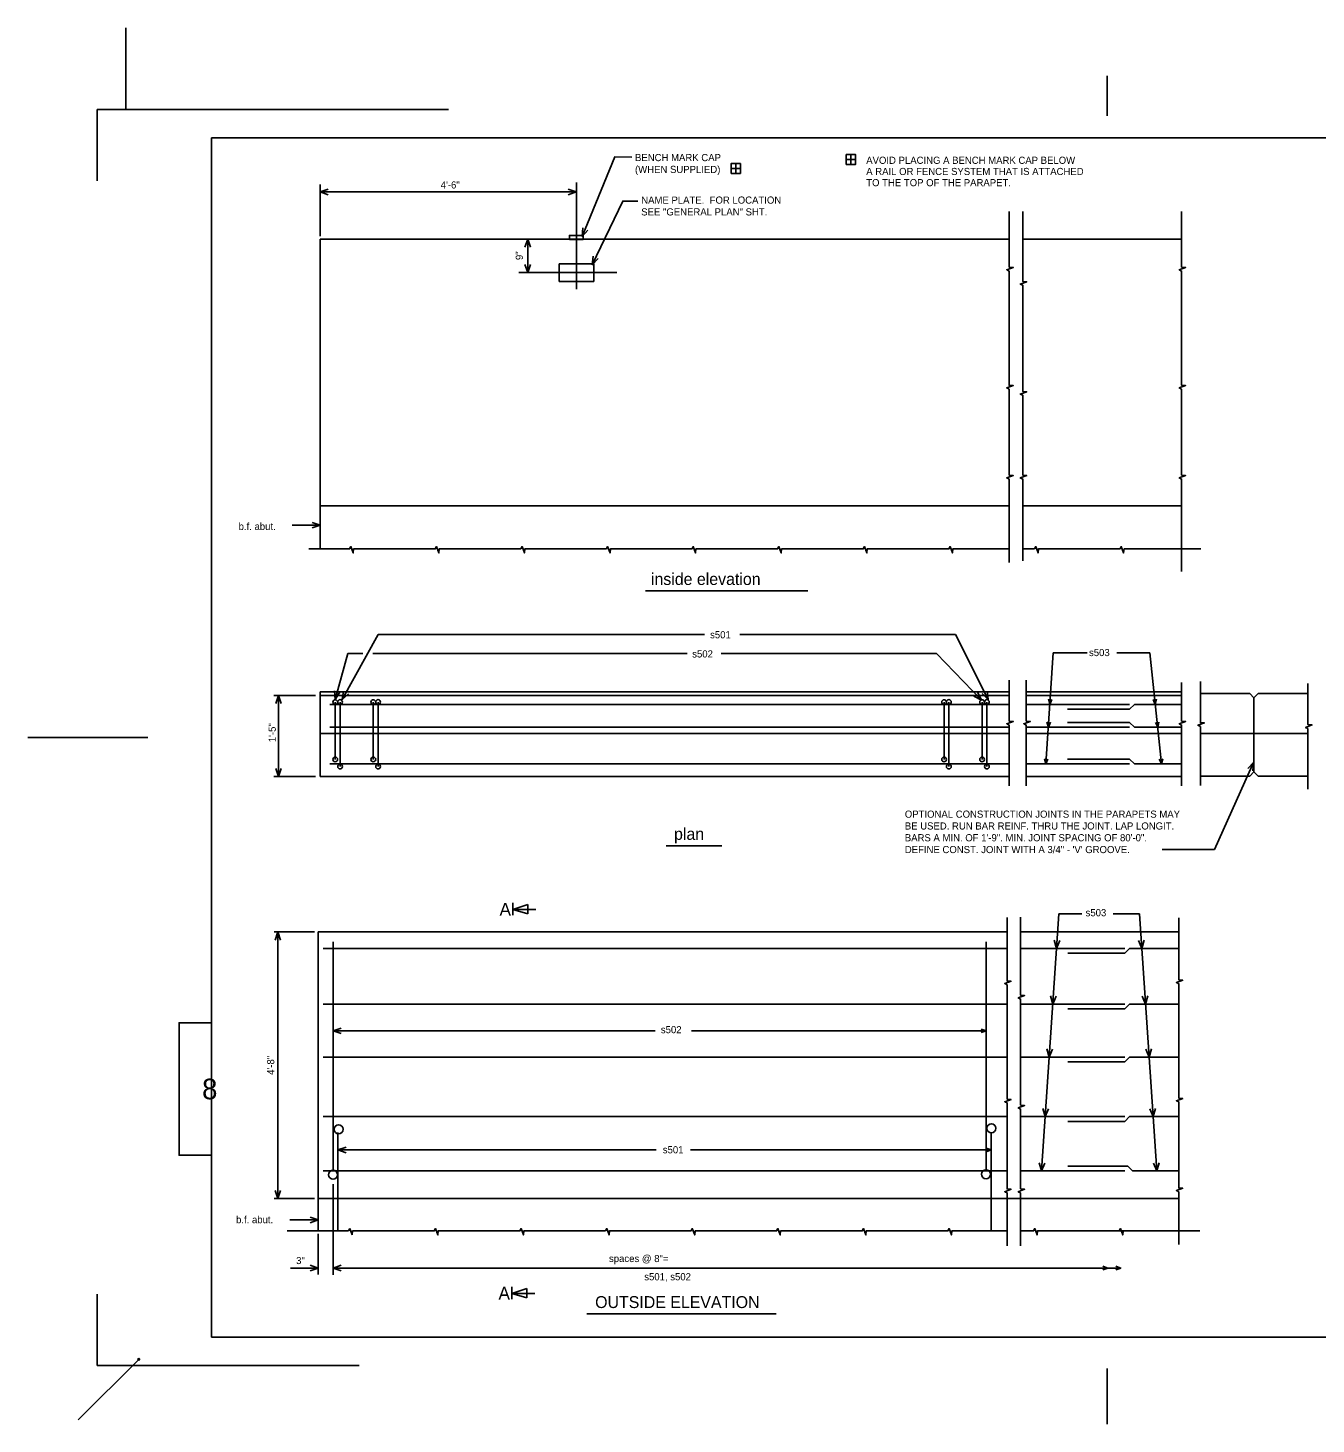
# Model space of a CAD drawing. Extents: x -38.4 to -2.2, y 84.9 to 109.4.
# Drawn here: x -38.4 to -15.84, y 84.95 to 109.4 of the extents above; entities that cross this region are included whole.
import ezdxf

# ---------------------------------------------------------------- set-up
doc = ezdxf.new("R2010")
doc.units = 0
for name, color, linetype in [('Default', 7, 'Continuous'), ('Level 1', 7, 'Continuous'), ('Level 2', 7, 'Continuous'), ('Level 37', 7, 'Continuous'), ('Level 49', 7, 'Continuous')]:
    doc.layers.add(name, color=color, linetype=linetype)

msp = doc.modelspace()

# ---------------------------------------------------------------- linework, layer by layer
at = {"layer": 'Default'}
for p, q in [((-33.278, 105.749), (-33.278, 106.654)), ((-28.787, 104.825), (-28.787, 106.689)), ((-33.278, 106.525), (-28.778, 106.525)), ((-21.212, 105.695), (-33.278, 105.695)), ((-33.278, 105.695), (-33.278, 101.028)), ((-29.644, 105.115), (-29.644, 105.698)), ((-18.191, 105.695), (-20.974, 105.695)), ((-29.095, 104.958), (-29.095, 105.264)), ((-29.095, 105.264), (-28.486, 105.264)), ((-28.486, 104.958), (-28.486, 105.264)), ((-29.801, 105.115), (-28.081, 105.115)), ((-29.095, 104.958), (-28.486, 104.958)), ((-33.278, 103.695), (-33.278, 103.664)), ((-21.212, 101.028), (-33.278, 101.028)), ((-33.278, 101.028), (-33.278, 100.274)), ((-18.191, 101.028), (-20.974, 101.028)), ((-33.772, 100.689), (-33.278, 100.689)), ((-27.579, 99.537), (-24.74, 99.537)), ((-32.897, 97.637), (-32.261, 98.773)), ((-32.261, 98.773), (-26.545, 98.773)), ((-25.929, 98.773), (-22.151, 98.773)), ((-21.577, 97.635), (-22.151, 98.773)), ((-33.018, 97.639), (-32.795, 98.443)), ((-32.795, 98.443), (-32.532, 98.443)), ((-32.357, 98.443), (-26.849, 98.443)), ((-26.254, 98.443), (-22.485, 98.443)), ((-21.697, 97.625), (-22.485, 98.443)), ((-33.362, 97.706), (-34.092, 97.706)), ((-34.008, 96.289), (-34.008, 97.706)), ((-21.212, 97.768), (-33.278, 97.768)), ((-33.278, 96.289), (-33.278, 97.768)), ((-21.212, 97.706), (-33.278, 97.706)), ((-33.016, 97.591), (-33.016, 96.587)), ((-32.931, 97.592), (-32.931, 96.462)), ((-32.349, 97.591), (-32.349, 96.587)), ((-32.265, 97.592), (-32.265, 96.462)), ((-22.352, 97.591), (-22.352, 96.587)), ((-22.268, 97.592), (-22.268, 96.462)), ((-21.686, 97.591), (-21.686, 96.587)), ((-21.601, 97.592), (-21.601, 96.462)), ((-18.191, 97.768), (-20.913, 97.768)), ((-18.191, 97.706), (-20.913, 97.706)), ((-17.863, 97.744), (-16.996, 97.744)), ((-16.925, 97.664), (-16.996, 97.744)), ((-16.853, 97.744), (-16.925, 97.664)), ((-16.925, 97.664), (-16.925, 96.368)), ((-16.853, 97.744), (-15.978, 97.744)), ((-21.212, 97.551), (-33.112, 97.551)), ((-19.101, 97.551), (-20.913, 97.551)), ((-19.101, 97.467), (-20.187, 97.467)), ((-18.191, 97.551), (-19.017, 97.551)), ((-21.212, 97.151), (-33.112, 97.151)), ((-19.101, 97.151), (-20.913, 97.151)), ((-19.101, 97.235), (-20.187, 97.235)), ((-18.191, 97.151), (-19.017, 97.151)), ((-21.212, 97.039), (-33.278, 97.039)), ((-20.913, 97.039), (-18.191, 97.039)), ((-17.863, 97.039), (-15.978, 97.039)), ((-20.187, 96.591), (-19.101, 96.591)), ((-33.112, 96.508), (-21.212, 96.508)), ((-20.913, 96.508), (-19.101, 96.508)), ((-19.017, 96.508), (-18.191, 96.508)), ((-17.614, 95.012), (-16.932, 96.533)), ((-16.925, 96.368), (-16.997, 96.296)), ((-16.925, 96.368), (-16.853, 96.296)), ((-33.362, 96.289), (-34.092, 96.289)), ((-21.212, 96.289), (-33.278, 96.289)), ((-18.191, 96.289), (-20.913, 96.289)), ((-17.863, 96.296), (-16.997, 96.296)), ((-16.853, 96.296), (-15.978, 96.296)), ((-27.221, 95.073), (-26.243, 95.073)), ((-18.53, 95.012), (-17.614, 95.012)), ((-29.907, 94.073), (-29.907, 93.858)), ((-29.907, 93.956), (-29.643, 94.044)), ((-29.643, 93.88), (-29.907, 93.956)), ((-29.907, 93.956), (-29.502, 93.956)), ((-29.643, 94.044), (-29.643, 93.88)), ((-20.645, 89.381), (-20.343, 93.882)), ((-20.343, 93.882), (-19.94, 93.882)), ((-18.927, 93.882), (-19.387, 93.882)), ((-18.625, 89.381), (-18.927, 93.882)), ((-33.378, 93.565), (-34.084, 93.565)), ((-34.021, 93.565), (-34.021, 88.898)), ((-33.315, 93.565), (-33.315, 88.329)), ((-33.315, 93.565), (-21.249, 93.565)), ((-21.011, 93.565), (-18.241, 93.565)), ((-21.249, 93.275), (-33.228, 93.275)), ((-33.053, 93.391), (-33.053, 89.381)), ((-21.614, 93.391), (-21.614, 89.381)), ((-19.184, 93.275), (-21.011, 93.275)), ((-19.184, 93.192), (-20.184, 93.192)), ((-18.241, 93.275), (-19.101, 93.275)), ((-21.249, 92.302), (-33.228, 92.302)), ((-19.184, 92.302), (-21.011, 92.302)), ((-19.184, 92.219), (-20.184, 92.219)), ((-18.241, 92.302), (-19.101, 92.302)), ((-33.053, 91.833), (-27.412, 91.833)), ((-26.776, 91.833), (-21.614, 91.833)), ((-21.249, 91.374), (-33.228, 91.374)), ((-19.184, 91.374), (-21.011, 91.374)), ((-19.184, 91.291), (-20.184, 91.291)), ((-18.241, 91.374), (-19.101, 91.374)), ((-21.249, 90.331), (-33.228, 90.331)), ((-19.184, 90.331), (-21.011, 90.331)), ((-19.184, 90.248), (-20.184, 90.248)), ((-18.241, 90.331), (-19.101, 90.331)), ((-32.968, 90.053), (-32.968, 88.329)), ((-21.529, 90.053), (-21.529, 88.329)), ((-32.968, 89.747), (-27.395, 89.747)), ((-26.795, 89.747), (-21.529, 89.747)), ((-21.249, 89.381), (-33.228, 89.381)), ((-19.184, 89.381), (-21.011, 89.381)), ((-19.135, 89.464), (-20.184, 89.464)), ((-18.241, 89.381), (-19.052, 89.381)), ((-33.053, 89.147), (-33.053, 87.563)), ((-33.378, 88.898), (-34.084, 88.898)), ((-33.315, 88.898), (-18.241, 88.898)), ((-33.808, 88.521), (-33.315, 88.521)), ((-33.855, 88.329), (-32.781, 88.329)), ((-33.315, 88.279), (-33.315, 87.568)), ((-32.781, 88.329), (-32.759, 88.371)), ((-32.759, 88.371), (-32.718, 88.259)), ((-32.718, 88.259), (-32.712, 88.329)), ((-32.712, 88.329), (-31.994, 88.329)), ((-33.802, 87.679), (-33.315, 87.679)), ((-33.053, 87.679), (-19.256, 87.679)), ((-19.908, 87.679), (-19.908, 87.679)), ((-29.924, 87.351), (-29.924, 87.135)), ((-29.924, 87.234), (-29.661, 87.322)), ((-29.661, 87.322), (-29.661, 87.158)), ((-29.661, 87.158), (-29.924, 87.234)), ((-29.924, 87.234), (-29.52, 87.234)), ((-28.606, 86.877), (-25.295, 86.877))]:
    msp.add_line(p, q, dxfattribs=at)
for points in [[(-28.69, 105.745), (-28.12, 107.137), (-27.82, 107.136)], [(-33.138, 106.476), (-33.278, 106.525), (-33.138, 106.573)], [(-28.936, 106.573), (-28.795, 106.525), (-28.936, 106.476)], [(-28.513, 105.251), (-27.981, 106.365), (-27.716, 106.365)], [(-21.212, 104.428), (-21.212, 105.14), (-21.253, 105.161), (-21.141, 105.203), (-21.212, 105.209), (-21.212, 106.181)], [(-20.974, 104.071), (-20.974, 104.89), (-21.016, 104.911), (-20.904, 104.952), (-20.974, 104.958), (-20.974, 106.181)], [(-18.191, 104.428), (-18.191, 105.14), (-18.233, 105.161), (-18.121, 105.203), (-18.191, 105.209), (-18.191, 106.181)], [(-28.591, 105.857), (-28.69, 105.745), (-28.681, 105.894)], [(-29.693, 105.557), (-29.644, 105.698), (-29.596, 105.557)], [(-28.408, 105.357), (-28.513, 105.251), (-28.496, 105.399)], [(-29.596, 105.256), (-29.644, 105.115), (-29.693, 105.256)], [(-21.212, 102.538), (-21.212, 103.07), (-21.253, 103.092), (-21.141, 103.133), (-21.212, 103.139), (-21.212, 104.421)], [(-18.191, 102.538), (-18.191, 103.07), (-18.233, 103.092), (-18.121, 103.133), (-18.191, 103.139), (-18.191, 104.421)], [(-20.974, 102.538), (-20.974, 102.964), (-21.016, 102.985), (-20.904, 103.027), (-20.974, 103.033), (-20.974, 104.158)], [(-21.212, 100.036), (-21.212, 101.496), (-21.253, 101.518), (-21.141, 101.559), (-21.212, 101.565), (-21.212, 102.538)], [(-20.974, 100.064), (-20.974, 101.496), (-21.016, 101.518), (-20.904, 101.559), (-20.974, 101.565), (-20.974, 102.538)], [(-18.191, 99.879), (-18.191, 101.496), (-18.233, 101.518), (-18.121, 101.559), (-18.191, 101.565), (-18.191, 102.538)], [(-33.419, 100.737), (-33.278, 100.689), (-33.419, 100.64)], [(-33.476, 100.274), (-32.764, 100.274), (-32.742, 100.315), (-32.701, 100.203), (-32.695, 100.274), (-31.976, 100.274)], [(-31.976, 100.274), (-31.264, 100.274), (-31.243, 100.315), (-31.201, 100.203), (-31.195, 100.274), (-30.477, 100.274)], [(-30.477, 100.274), (-29.765, 100.274), (-29.743, 100.315), (-29.702, 100.203), (-29.696, 100.274), (-28.978, 100.274)], [(-28.978, 100.274), (-28.265, 100.274), (-28.244, 100.315), (-28.202, 100.203), (-28.197, 100.274), (-27.478, 100.274)], [(-27.478, 100.274), (-26.766, 100.274), (-26.744, 100.315), (-26.703, 100.203), (-26.697, 100.274), (-25.979, 100.274)], [(-25.979, 100.274), (-25.267, 100.274), (-25.245, 100.315), (-25.204, 100.203), (-25.198, 100.274), (-24.479, 100.274)], [(-24.479, 100.274), (-23.767, 100.274), (-23.745, 100.315), (-23.704, 100.203), (-23.698, 100.274), (-22.98, 100.274)], [(-22.98, 100.274), (-22.268, 100.274), (-22.246, 100.315), (-22.205, 100.203), (-22.199, 100.274), (-21.48, 100.274)], [(-21.48, 100.274), (-21.212, 100.274)], [(-20.974, 100.274), (-20.768, 100.274), (-20.747, 100.315), (-20.705, 100.203), (-20.699, 100.274), (-19.981, 100.274)], [(-19.981, 100.274), (-19.269, 100.274), (-19.247, 100.315), (-19.206, 100.203), (-19.2, 100.274), (-17.852, 100.274)], [(-21.212, 96.127), (-21.212, 97.189), (-21.253, 97.211), (-21.141, 97.252), (-21.212, 97.258), (-21.212, 97.977)], [(-20.913, 96.127), (-20.913, 97.189), (-20.955, 97.211), (-20.843, 97.252), (-20.913, 97.258), (-20.913, 97.977)], [(-18.191, 96.127), (-18.191, 97.189), (-18.233, 97.211), (-18.121, 97.252), (-18.191, 97.258), (-18.191, 97.936)], [(-17.863, 96.132), (-17.863, 97.162), (-17.905, 97.184), (-17.793, 97.225), (-17.863, 97.231), (-17.863, 97.949)], [(-15.978, 96.064), (-15.978, 97.127), (-16.019, 97.148), (-15.907, 97.19), (-15.978, 97.196), (-15.978, 97.914)], [(-34.057, 97.565), (-34.008, 97.706), (-33.96, 97.565)], [(-32.934, 97.762), (-33.018, 97.639), (-33.028, 97.788)], [(-32.786, 97.736), (-32.897, 97.637), (-32.871, 97.783)], [(-21.76, 97.761), (-21.697, 97.625), (-21.83, 97.693)], [(-21.597, 97.783), (-21.577, 97.635), (-21.684, 97.739)], [(-33.96, 96.43), (-34.008, 96.289), (-34.057, 96.43)], [(-17.034, 96.425), (-16.932, 96.533), (-16.945, 96.385)], [(-21.249, 91.927), (-21.249, 92.639), (-21.29, 92.661), (-21.178, 92.702), (-21.249, 92.708), (-21.249, 93.818)], [(-21.011, 91.571), (-21.011, 92.389), (-21.052, 92.411), (-20.94, 92.452), (-21.011, 92.458), (-21.011, 93.825)], [(-18.241, 91.946), (-18.241, 92.658), (-18.283, 92.679), (-18.171, 92.721), (-18.241, 92.727), (-18.241, 93.812)], [(-34.07, 93.424), (-34.021, 93.565), (-33.972, 93.424)], [(-20.326, 93.413), (-20.384, 93.275), (-20.423, 93.419)], [(-18.944, 93.413), (-18.886, 93.275), (-18.847, 93.419)], [(-20.391, 92.439), (-20.449, 92.302), (-20.489, 92.446)], [(-18.879, 92.439), (-18.821, 92.302), (-18.781, 92.446)], [(-18.241, 90.055), (-18.241, 90.588), (-18.283, 90.61), (-18.171, 90.651), (-18.241, 90.657), (-18.241, 91.939)], [(-32.912, 91.785), (-33.053, 91.833), (-32.912, 91.882)], [(-21.702, 91.864), (-21.614, 91.833), (-21.702, 91.803)], [(-21.249, 90.037), (-21.249, 90.57), (-21.29, 90.591), (-21.178, 90.633), (-21.249, 90.638), (-21.249, 91.921)], [(-21.011, 90.037), (-21.011, 90.463), (-21.052, 90.485), (-20.94, 90.526), (-21.011, 90.532), (-21.011, 91.657)], [(-20.454, 91.512), (-20.512, 91.374), (-20.551, 91.518)], [(-18.816, 91.512), (-18.758, 91.374), (-18.719, 91.518)], [(-20.524, 90.468), (-20.582, 90.331), (-20.621, 90.475)], [(-18.746, 90.468), (-18.688, 90.331), (-18.649, 90.475)], [(-21.249, 88.07), (-21.249, 88.996), (-21.29, 89.017), (-21.178, 89.059), (-21.249, 89.065), (-21.249, 90.037)], [(-21.011, 88.07), (-21.011, 88.996), (-21.052, 89.017), (-20.94, 89.059), (-21.011, 89.065), (-21.011, 90.037)], [(-18.241, 88.089), (-18.241, 89.014), (-18.283, 89.036), (-18.171, 89.077), (-18.241, 89.083), (-18.241, 90.055)], [(-32.827, 89.698), (-32.968, 89.747), (-32.827, 89.796)], [(-21.617, 89.777), (-21.529, 89.747), (-21.617, 89.717)], [(-20.587, 89.518), (-20.645, 89.381), (-20.684, 89.524)], [(-18.683, 89.518), (-18.625, 89.381), (-18.586, 89.524)], [(-33.972, 89.039), (-34.021, 88.898), (-34.07, 89.039)], [(-33.456, 88.569), (-33.315, 88.521), (-33.456, 88.472)], [(-31.994, 88.329), (-31.281, 88.329), (-31.26, 88.371), (-31.218, 88.259), (-31.213, 88.329), (-30.494, 88.329)], [(-30.494, 88.329), (-29.782, 88.329), (-29.76, 88.371), (-29.719, 88.259), (-29.713, 88.329), (-28.995, 88.329)], [(-28.995, 88.329), (-28.283, 88.329), (-28.261, 88.371), (-28.22, 88.259), (-28.214, 88.329), (-27.495, 88.329)], [(-27.495, 88.329), (-26.783, 88.329), (-26.761, 88.371), (-26.72, 88.259), (-26.714, 88.329), (-25.996, 88.329)], [(-25.996, 88.329), (-25.284, 88.329), (-25.262, 88.371), (-25.221, 88.259), (-25.215, 88.329), (-24.496, 88.329)], [(-24.496, 88.329), (-23.784, 88.329), (-23.763, 88.371), (-23.721, 88.259), (-23.715, 88.329), (-22.997, 88.329)], [(-22.997, 88.329), (-22.285, 88.329), (-22.263, 88.371), (-22.222, 88.259), (-22.216, 88.329), (-21.249, 88.329)], [(-21.011, 88.329), (-20.785, 88.329), (-20.764, 88.371), (-20.723, 88.259), (-20.717, 88.329), (-18.241, 88.329)], [(-19.998, 88.329), (-19.286, 88.329), (-19.264, 88.371), (-19.223, 88.259), (-19.217, 88.329), (-17.869, 88.329)], [(-33.456, 87.728), (-33.315, 87.679), (-33.456, 87.631)], [(-32.912, 87.631), (-33.053, 87.679), (-32.912, 87.728)]]:
    msp.add_lwpolyline(points, dxfattribs=at)
for points in [[(-24.065, 107.007), (-24.065, 107.179), (-23.902, 107.179), (-23.902, 107.007)], [(-24.065, 107.093), (-24.065, 107.179), (-23.983, 107.179), (-23.983, 107.093)], [(-23.983, 107.007), (-23.983, 107.093), (-23.902, 107.093), (-23.902, 107.007)], [(-26.083, 106.849), (-26.083, 107.021), (-25.919, 107.021), (-25.919, 106.849)], [(-26.083, 106.935), (-26.083, 107.021), (-26.001, 107.021), (-26.001, 106.935)], [(-26.001, 106.849), (-26.001, 106.935), (-25.919, 106.935), (-25.919, 106.849)], [(-28.914, 105.694), (-28.674, 105.694), (-28.674, 105.763), (-28.914, 105.763)]]:
    msp.add_lwpolyline(points, close=True, dxfattribs=at)
for centre, radius in [((-33.016, 97.591), 0.0417), ((-32.931, 97.592), 0.0417), ((-32.349, 97.591), 0.0417), ((-32.265, 97.592), 0.0417), ((-22.352, 97.591), 0.0417), ((-22.268, 97.592), 0.0417), ((-21.686, 97.591), 0.0417), ((-21.601, 97.592), 0.0417), ((-33.016, 96.587), 0.0417), ((-32.349, 96.587), 0.0417), ((-22.352, 96.587), 0.0417), ((-21.686, 96.587), 0.0417), ((-32.931, 96.462), 0.0417), ((-32.265, 96.462), 0.0417), ((-22.268, 96.462), 0.0417), ((-21.601, 96.462), 0.0417), ((-32.958, 90.109), 0.0788), ((-21.522, 90.127), 0.0788), ((-33.053, 89.313), 0.0788), ((-21.617, 89.323), 0.0788)]:
    msp.add_circle(centre, radius, dxfattribs=at)
at = {"layer": 'Level 1'}
for p, q in [((-31.034, 107.971), (-37.185, 107.971)), ((-37.185, 107.971), (-37.185, 106.718)), ((-35.185, 86.471), (-35.185, 107.471)), ((-3.809, 107.471), (-35.185, 107.471)), ((-37.185, 87.224), (-37.185, 85.971)), ((-35.185, 86.471), (-3.809, 86.471)), ((-37.185, 85.971), (-32.597, 85.971))]:
    msp.add_line(p, q, dxfattribs=at)
msp.add_lwpolyline([(-35.185, 91.976), (-35.752, 91.976), (-35.752, 89.654), (-35.185, 89.654)], close=True, dxfattribs=at)
at = {"layer": 'Level 2'}
for p, q in [((-36.685, 107.971), (-36.685, 109.397)), ((-20.568, 96.508), (-20.438, 98.456)), ((-20.438, 98.456), (-19.843, 98.456)), ((-19.323, 98.456), (-18.747, 98.456)), ((-18.542, 96.508), (-18.747, 98.456)), ((-19.101, 97.467), (-19.017, 97.551)), ((-19.101, 97.235), (-19.017, 97.151)), ((-19.101, 96.591), (-19.017, 96.508)), ((-19.184, 93.192), (-19.101, 93.275)), ((-19.184, 92.219), (-19.101, 92.302)), ((-19.184, 91.291), (-19.101, 91.374)), ((-19.184, 90.248), (-19.101, 90.331)), ((-19.052, 89.381), (-19.135, 89.464)), ((-37.517, 85.02), (-36.456, 86.08))]:
    msp.add_line(p, q, dxfattribs=at)
for points in [[(-20.463, 97.637), (-20.499, 97.551), (-20.523, 97.641)], [(-18.631, 97.642), (-18.652, 97.551), (-18.691, 97.635)], [(-20.489, 97.237), (-20.525, 97.151), (-20.55, 97.241)], [(-18.589, 97.242), (-18.61, 97.151), (-18.649, 97.236)], [(-20.532, 96.593), (-20.568, 96.508), (-20.593, 96.598)], [(-18.521, 96.598), (-18.542, 96.508), (-18.582, 96.592)], [(-19.57, 87.71), (-19.482, 87.679), (-19.57, 87.649)], [(-19.344, 87.71), (-19.256, 87.679), (-19.344, 87.649)]]:
    msp.add_lwpolyline(points, dxfattribs=at)
at = {"layer": 'Level 37'}
for p, q in [((-19.497, 107.859), (-19.497, 108.559)), ((-36.299, 96.971), (-38.398, 96.971)), ((-19.497, 85.92), (-19.497, 84.947))]:
    msp.add_line(p, q, dxfattribs=at)
at = {"layer": 'Level 49'}
msp.add_circle((-36.457, 86.08), 0.0152, dxfattribs=at)

# ---------------------------------------------------------------- texts
at = {"layer": 'Default'}
for s, height, p in [('BENCH MARK CAP', 0.12503, (-27.765, 107.064)), ('AVOID PLACING A BENCH MARK CAP BELOW', 0.125, (-23.715, 107.017)), ('(WHEN SUPPLIED)', 0.12503, (-27.765, 106.857)), ('A RAIL OR FENCE SYSTEM THAT IS ATTACHED', 0.125, (-23.715, 106.821)), ('4\'-6"', 0.125, (-31.168, 106.585)), ('TO THE TOP OF THE PARAPET.', 0.125, (-23.715, 106.625)), ('NAME PLATE.  FOR LOCATION', 0.12503, (-27.656, 106.32)), ('SEE "GENERAL PLAN" SHT.', 0.12503, (-27.656, 106.113)), ('b.f. abut.', 0.125, (-34.708, 100.605)), ('inside elevation', 0.20834, (-27.486, 99.642)), ('s501', 0.125, (-26.45, 98.708)), ('s502', 0.125, (-26.763, 98.372)), ('s503', 0.125, (-19.813, 98.396)), ('OPTIONAL CONSTRUCTION JOINTS IN THE PARAPETS MAY ', 0.125, (-23.039, 95.566)), ('plan', 0.2083, (-27.081, 95.178)), ('BE USED. RUN BAR REINF. THRU THE JOINT. LAP LONGIT. ', 0.125, (-23.039, 95.359)), ('BARS A MIN. OF 1\'-9". MIN. JOINT SPACING OF 80\'-0".', 0.125, (-23.039, 95.153)), ('DEFINE CONST. JOINT WITH A 3/4" - \'V\' GROOVE.', 0.125, (-23.039, 94.946)), ('A', 0.225, (-30.138, 93.85)), ('s503', 0.125, (-19.873, 93.84)), ('s502', 0.125, (-27.312, 91.792)), ('s501', 0.125, (-27.278, 89.689)), ('b.f. abut.', 0.125, (-34.753, 88.465)), ('3"', 0.125, (-33.7, 87.749)), ('   spaces @ 8"=        ', 0.125, (-28.36, 87.784)), ('s501, s502', 0.125, (-27.603, 87.465)), ('A', 0.225, (-30.156, 87.127)), ('OUTSIDE ELEVATION', 0.20834, (-28.463, 86.979))]:
    msp.add_text(s, height=height, dxfattribs=at).set_placement(p)
for s, p in [('9"', (-29.73, 105.332)), ('1\'-5"', (-34.057, 96.888)), ('4\'-8"', (-34.084, 91.063))]:
    msp.add_text(s, height=0.125, rotation=90, dxfattribs=at).set_placement(p)
at = {"layer": 'Level 1'}
msp.add_text('8', height=0.361, dxfattribs=at).set_placement((-35.348, 90.635))

doc.saveas('drawing.dxf')
